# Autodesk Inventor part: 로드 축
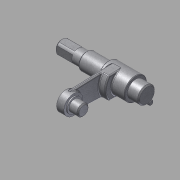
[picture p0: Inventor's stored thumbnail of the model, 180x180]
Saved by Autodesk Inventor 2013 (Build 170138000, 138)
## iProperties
Created: 2015-10
Part Number: 로드 축
Document SubType Name: Modeling
Designer: mdu
Density: 7.86 g/cm^3
Material: 강철, 연강
Mass: 157.934 g
Surface Area: 69.4485 cm^2
Volume: 20.0934 cm^3
Author: mdu
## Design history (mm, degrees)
sketch "스케치1"
  geometry: L1 (-3.325, 13.5)-(-3.325, -13.5) reference; L2 (48.675, -15.7)-(48.675, 15.7) reference; L3 (48.675, 0)-(-26.325, 0); L4 (39.675, -18.06)-(39.675, 18.06) reference; L5 (15.675, 18.855)-(15.675, -18.855) reference; L6 (6.675, 15.7)-(6.675, -15.7) reference; L7 (3.675, -10)-(3.675, 10) reference; L8 (49.675, 7.5)-(39.675, 7.5); L9 (39.675, 7.5)-(39.675, 10); L10 (39.675, 10)-(15.675, 10); L11 (15.675, 10)-(15.675, 7.5); L12 (15.675, 7.5)-(-4.325, 7.5); L13 (-4.325, 7.5)-(-4.325, 6); L14 (-4.325, 6)-(-26.325, 6); L15 (-26.325, 6)-(-26.325, 0); L16 (48.675, 0)-(49.675, 0); L17 (49.675, 0)-(49.675, 7.5); 1 further point
  constraints: 22 end point, 7 perpendicular, 4 point on line, 2 parallel, 1 collinear, 1 midpoint
  dimensions: "d0" = 15 diameter of L8 L3; "d1" = 20 diameter of L10 L3; "d2" = 12 diameter of L14 L3; "d3" = 20 distance of L11.end L12.end; "d4" = 1 distance between parallel lines of L17 L2; "d5" = 75 distance of L3.start L3.end
revolve "회전1" sketch "스케치1" stored, may be unused: angle "d6" = 90 deg
chamfer "모따기1" distance "d7" = 1; stored, may be unused: second distance "d8" = 2, angle "d9" = 45 deg
node "작업 평면1"
sketch "스케치2"
  geometry: 1 further point
sketch "스케치3"
  geometry: L1 (9.993, -0.375)-(8.494, -40.319); L2 (-8.494, -40.319)-(-9.993, -0.375); C1 r 10 at (0, 0) reference; A1 r 8.5 centre (0, -40) between (8.494, -40.319) and (-8.494, -40.319); A2 r 10 centre (0, 0) between (-9.993, -0.375) and (9.993, -0.375) reference; 1 further point
  constraints: 4 end point, 4 point on circle, 4 tangent, 1 centre point, 1 vertical alignment
  dimensions: "d12" = 17 diameter of A1; "d22" = 40 distance of A1.centre A2.centre
  node "투영된 루프1"
extrude "돌출1" join sketch "스케치3" distance "d13" = 6.5; taper "d14" = 0 deg
node "작업 평면3"
  node "작업 평면2"
extrude "돌출2" join sketch "스케치3" stored distance "d17" = 6; taper "d18" = 0 deg
sketch "스케치7"
  geometry: L1 (-9.993, -0.375)-(-8.494, -40.319) reference; L2 (8.494, -40.319)-(9.993, -0.375) reference; A1 r 10 centre (0, 0) between (-9.993, -0.375) and (9.993, -0.375) reference; A2 r 15 centre (0, 0) between (-9.574, -11.547) and (9.574, -11.547); 1 further point
  constraints: 2 point on circle, 2 point on line, 1 centre point, 1 coincident
  dimensions: "d32" = 30 diameter of A2
extrude "돌출6" join sketch "스케치7" distance "d33" = 6; taper "d34" = 0 deg
sketch "스케치5"
  geometry: C1 r 5 at (0, 0) reference; C2 r 6.5 at (0, 0); 1 further point
  constraints: 1 centre point, 1 coincident
  dimensions: "d23" = 13 diameter of C2
  node "참조8"
extrude "돌출4" join sketch "스케치5" distance "d24" = 9; taper "d25" = 0 deg
extrude "돌출5" join sketch "스케치5" distance "d26" = 1; taper "d27" = 0 deg
fillet "모깎기1" dims "d28" = 1
chamfer "모따기2" distance "d29" = 1; stored, may be unused: second distance "d30" = 2, angle "d31" = 45 deg
chamfer "모따기3" distance "d35" = 0.5; stored, may be unused: second distance "d36" = 2, angle "d37" = 45 deg
sketch "스케치8"
  geometry: L1 (-3.25, 5.044)-(3.25, 5.044); L2 (5.044, 3.25)-(5.044, -3.25); L3 (3.25, -5.044)-(-3.25, -5.044); L4 (-5.044, -3.25)-(-5.044, 3.25); 2 further points
  constraints: 8 end point, 6 perpendicular, 1 horizontal, 9 other
  dimensions: "d38" = 6.5 distance of L3.start L3.end
extrude "돌출7" cut sketch "스케치8" distance "d39" = 15; taper "d40" = 0 deg
node "작업 평면4"
sketch "스케치9"
  geometry: L1 (7.66, 6.428)-(25.279, 21.212); L2 (23.973, 23.344)-(1.901, 9.818); L3 (27.152, 19.555)-(9.999, 0.167); L4 (28.659, 0)-(-16.444, 0) reference; C1 r 2 at (25.279, 21.212); A1 r 10 centre (0, 0) between (7.66, 6.428) and (1.901, 9.818) reference; A2 r 2.5 centre (25.279, 21.212) between (23.973, 23.344) and (27.152, 19.555); 1 further point
  constraints: 6 end point, 5 point on circle, 2 centre point, 2 coincident, 2 tangent, 1 point on line
  dimensions: "d42" = 23 distance of L1.start L1.end; "d43" = 5 diameter of A2; "d44" = 17 deg angle of L3 L2; "d45" = 8.5 deg angle of L1 L2 (= 0.5 x d44); "d46" = 40 deg angle of L4 L1; "d54" = 4 diameter of C1
extrude "돌출8" join sketch "스케치9" stored distance "d47" = 3; taper "d48" = 0 deg
extrude "돌출9" join sketch "스케치9" stored distance "d49" = 4; taper "d50" = 0 deg
fillet "모깎기2" dims "d51" = 1
fillet "모깎기3" dims "d52" = 1
fillet "모깎기4" dims "d53" = 1
extrude "돌출10" join sketch "스케치9" stored distance "d55" = 15; taper "d56" = 0 deg
chamfer "모따기4" distance "d57" = 0.5; stored, may be unused: second distance "d58" = 2, angle "d59" = 45 deg
node "솔리드1"
node "참조1"
node "참조2"
node "참조3"
node "참조4"
node "참조5"
node "참조6"
other parameters: "d10" = -8.5, "d15" = -1, "d16" = -3, "d41" = -15
